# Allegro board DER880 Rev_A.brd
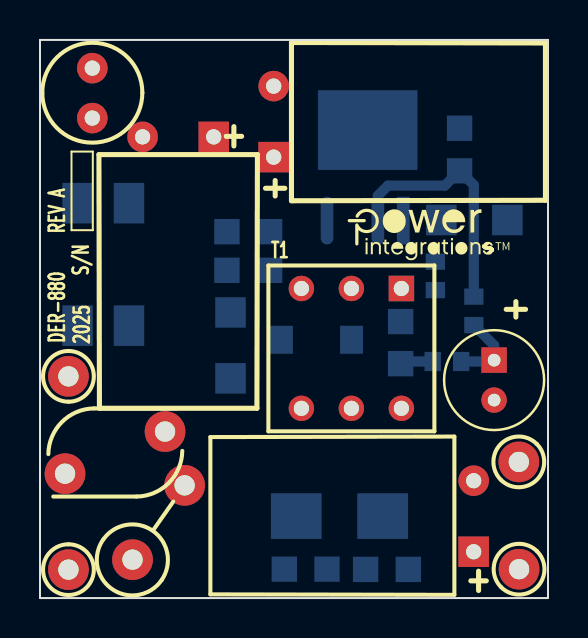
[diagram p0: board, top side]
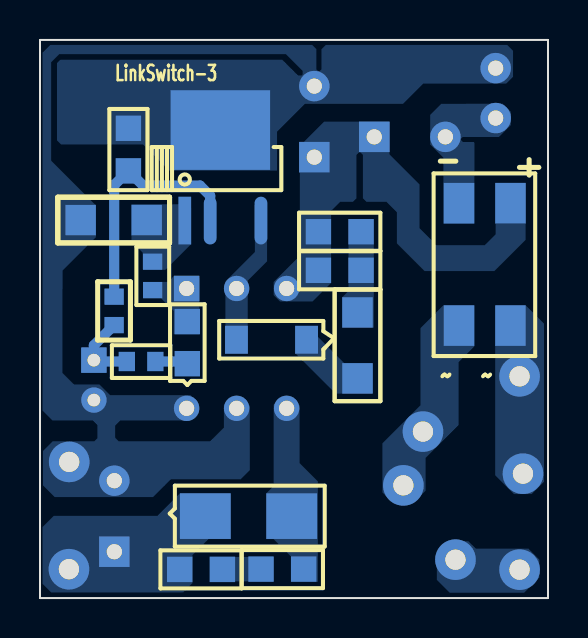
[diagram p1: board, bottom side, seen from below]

Outline 25.4 x 27.94 mm; copper layers: TOP, BOTTOM. Coordinates in mm from the lower left corner of the outline.
Outline path: 0,27.94 0,0 25.4,0 25.4,27.94 0,27.94

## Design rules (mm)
constraint set DEFAULT: min track width 0.508

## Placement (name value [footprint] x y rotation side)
BR1  B10S-G  [PISMSOIC4]  4.45 13.64 180 bottom
C1  3.3 uF  [PIPOLCAPCLYD320LS140030]  6.91 23.09 180 top
C2  3.3 uF  [PIPOLCAPCLYD320LS140030#2]  11.68 23.85 270 top
C3  10 uF  [PIPOLCAPCLYD5MMLS2MM025]  22.71 10.91 270 top
C4  1 uF  [PISMC0805]  20.98 21.39 90 bottom
C5  470 pF  [PISMC0805]  11.48 18.34 180 bottom
C7  470 pF  [PISMC0805]  16.28 1.44 0 bottom
C8  470  uF  [PIPOLCAPCLYD320LS140030]  21.68 4.1 90 top
D2  BAV20WS-7-F  [PISMDSOD323]  18.03 11.73 90 bottom
D3  S1ML  [PI_SM_SOD-123_12]  12.07 12.93 0 bottom
D4  SS110-TP  [PISMDO214AC12]  17.13 4.1 180 bottom
GND  -  [PITPKEYSTONE100X100]  23.94 6.82 315 top
L  BLK  [PITPKEYSTONE100X100]  1.42 1.42 0 top
L1  680 uH  [PICHOKETOKINVD216H413LS098D030]  2.62 24.03 90 top
N  WHT  [PITPKEYSTONE100X100]  1.42 11.1 0 top
NOREF  -  []  0 27.94 0 top
NOREF#2  -  []  0 0 90 top
NOREF#3  -  []  14.83 19.38 0 top
R1  100 k  [PISMR0805]  11.48 16.41 180 bottom
R2  470  [PISMR1206]  9.53 14.3 270 bottom
R3  57.6 k  [PISMR0603]  19.77 15.42 90 bottom
R4  12.7 k  [PISMR1206]  20.07 18.92 0 bottom
R5  9.1 k  [PISMR0603]  21.69 15.09 270 bottom
R6  10  [PISMR0603]  21.06 11.84 180 bottom
R8  15  [PISMR0805]  12.22 1.45 0 bottom
RF1  8.2  [PI12WRESD180LS575040]  4.63 1.92 55 top
RV1  275 Vac  [PI_DISC276X181_LS200X83D040]  6.25 6.23 180 top
T1  EE8.3  [PI_BOBBIN_EE8_3H6P]  15.57 12.5 270 top
U1  LNK6404D  [PISMSO8DNSHORT5678]  18.16 18.9 180 bottom
UNK+5V  RED  [PITPKEYSTONE100X100]  23.95 1.44 315 top

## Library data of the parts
BR1 = DIODE BRIDGE_~~+-: alternate symbols: (pi_sm_soic4_slot)
C1 C2 C8 = CAP POL: alternate symbols: (pipolcapclyd320ls140030430h)
C3 = CAP POL
C4 C5 C7 = CAP NP
D2 D3 = DIODE
D4 = DIODE SCHOTTKY
GND = TESTPOINT_PITPKEYSTONE100X100_B
L = TESTPOINT: alternate symbols: (TP_TH_CR2_D1_1)
L1 = INDUCTOR
N UNK+5V = TESTPOINT
R1-R6 R8 = R
RF1 = RF: alternate symbols: (pi1wvresd120ls200d040)
RV1 = VARISTOR
T1 = BEE8_3_6P
U1 = LNK6404

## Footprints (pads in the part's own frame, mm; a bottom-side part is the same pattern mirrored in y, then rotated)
PI12WRESD180LS575040
  round 2.032 hole 1.016: 1(0,0) 2(4.542,0)
PI_BOBBIN_EE8_3H6P
  rect 1.27x1.27 hole 0.762: 1(-3,2.5)
  round 1.27 hole 0.762: 2(-3,0) 3(-3,-2.5) 4(3,-2.5) 5(3,0) 6(3,2.5)
PI_DISC276X181_LS200X83D040
  round 2.032 hole 1.016: 1(0,-2.108) 2(5.001,0)
PI_SM_SOD-123_12
  rect 1.143x1.397 smd: 1(0,0) 2(3.505,0)
PICHOKETOKINVD216H413LS098D030
  round 1.524 hole 0.762: 1(0,0) 2(2.5,0)
PIPOLCAPCLYD5MMLS2MM025
  rect 1.27x1.27 hole 0.635: 1(-1,0)
  round 1.27 hole 0.635: 2(1,0)
PIPOLCAPCLYD320LS140030
  rect 1.524x1.524 hole 0.762: 1(-1.778,0)
  round 1.524 hole 0.762: 2(1.778,0)
PIPOLCAPCLYD320LS140030#2
  rect 1.524x1.524 hole 0.762: 1(1.778,0)
  round 1.524 hole 0.762: 2(-1.778,0)
PISMC0805
  rect 1.27x1.27 smd: 1(0,0) 2(2.134,0)
PISMDO214AC12
  rect 2.54x2.286 smd: 1(0,0) 2(4.318,0)
PISMDSOD323
  rect 1.27x1.27 smd: 1(0,0) 2(2.108,0)
PISMR0603
  rect 0.813x0.965 smd: 1(0,0) 2(1.422,0)
PISMR0805
  rect 1.27x1.27 smd: 1(0,0) 2(2.134,0)
PISMR1206
  rect 1.524x1.524 smd: 1(0,0) 2(3.302,0)
PISMSO8DNSHORT5678
  rect 0.635x2.388 smd: 1(0,0)
  oval 0.635x2.388 smd: 2(1.27,0) 4(3.81,0) 5(3.81,4.978) 6(2.54,4.978) 7(1.27,4.978) 8(0,4.978)
PISMSOIC4
  rect 1.524x2.032 smd: 1(0,0) 2(2.57,0) 3(2.57,6.129) 4(0,6.129)
PITPKEYSTONE100X100
  round 2.032 hole 1.016: 1(0,0)

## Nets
SOURCE: U1.6 U1.7 U1.8
N02548: BR1.3 C1.1 C2.1 C5.1 R1.1 T1.3
N02674: BR1.4 C1.2 L1.1
N03502: C2.2 C3.2 C4.2 C8.2 GND.1 L1.2 R4.2 T1.5 T1.6 U1.5(S)
N03550: C4.1 R5.1 U1.2
N04036: R3.2 R4.1 U1.1
N04459: C3.1 R5.2 R6.1
N04496: D2.1 R6.2
N04748: D3.2 T1.2 U1.4
N04766: D2.2 R3.1 T1.1
N04877: D4.2 R8.1 T1.4
N04912: C7.1 R8.2
N04991: C7.2 C8.1 D4.1 UNK+5V.1
N06108: BR1.1 RF1.2 RV1.1
N06154: L.1 RF1.1
N06177: BR1.2 N.1 RV1.2
N12152: C5.2 R1.2 R2.1
N12184: D3.1 R2.2

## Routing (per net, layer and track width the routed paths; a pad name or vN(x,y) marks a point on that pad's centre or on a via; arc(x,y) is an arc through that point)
N03550: length 12.4
  BOTTOM w0.508: U1.2 16.89,20.14 17.4,20.65 20.24,20.65 C4.1 21.69,20.67 R5.1
N04459: length 3.9
  BOTTOM w0.508: R6.1 22.64,11.84 C3.1 22.71,12.65 R5.2
N04496: length 1.6
  BOTTOM w0.508: D2.1 18.14,11.84 R6.2

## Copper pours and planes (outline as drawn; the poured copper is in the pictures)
N02548 on BOTTOM: 7.56,17.75 6.17,16.37 2.68,16.37 1.12,17.93 1.12,20.78 2.62,20.78 2.62,18.21 3.16,17.67 5.57,17.67 6.42,18.52 6.42,20.71 7.92,22.21 7.92,23.85 11.19,23.85 12.41,22.63 12.41,17.13 13.72,15.82 13.72,15.16 13.4,14.85 11.77,14.85 10.85,15.77 10.85,19.38 10.39,19.84 9.75,19.84 9.58,20.01 9.58,22.18 9.44,22.32 9.39,22.32 9.25,22.19 9.25,20.02 9.08,19.84 8.08,19.84 7.56,19.32
N02674 on BOTTOM: 3.68,18.75 3.68,21.18 3.68,21.19 3.68,22.79 3.72,22.83 4.25,22.83 4.36,22.94 4.36,22.99 4.27,23.08 2.45,23.08 1.86,23.68 1.86,24.34 2.26,24.75 4.09,24.75 4.09,24.74 5.34,24.74 5.89,24.19 5.89,22.71 5.23,22.05 5.23,18.75
N03502 on BOTTOM (solid shape): 18.87,21.44 13.89,21.44 13.89,25.43 18.87,25.43
N03502 on BOTTOM: 14.91,9.63 15.32,10.03 15.82,10.03 16.21,9.65 16.21,8.53 16.89,7.85 21.46,7.85 21.64,8.03 21.64,8.64 21.39,8.89 17.91,8.89 17.54,9.26 17.54,9.82 17.88,10.16 21.89,10.16 22.43,10.69 23.7,10.69 24.28,11.27 24.28,15.47 24.27,15.48 24.27,16.4 22.61,18.06 22.61,19.66 24.84,21.89 24.84,26.82 24.43,27.23 13.11,27.23 12.27,26.39 12.27,26.21 12.32,26.16 12.5,26.16 13.28,26.95 24.38,26.95 24.55,26.78 24.55,22.91 24.35,22.71 20.24,22.71 18.95,21.41 18.95,21.4 13.55,21.4 13.55,23.35 12.4,24.5 12.16,24.74 7.25,24.74 6.23,25.76 2.09,25.76 1.75,26.1 1.75,27.4 2.04,27.69 11.11,27.69 11.33,27.47 11.33,26.47 11.43,26.37 11.48,26.37 11.58,26.47 11.58,27.48 11.79,27.69 24.88,27.69 25.27,27.3 25.27,9.39 24.78,8.89 22.76,8.89 22.53,8.66 22.53,8 22.68,7.85 24.77,7.85 25.25,7.37 25.25,5.64 24.66,5.05 19.75,5.05 18.85,5.95 15.36,5.95 14.91,6.4
N04036 on BOTTOM: 17.84,17.7 17.86,17.7 19.13,16.43 20.24,16.43 20.27,16.46 20.27,17.3 20.83,17.86 20.83,19.71 18.01,19.71 17.84,19.54
N04748 on BOTTOM: 14.05,16.86 15.01,15.89 15.01,12.24 16.13,12.24 16.13,15.85 14.66,17.32 14.66,19.71 14.53,19.84 14.15,19.84 14.05,19.74
N04766 on BOTTOM: 18.72,13.21 18.72,14.38 19.35,15.01 20.24,15.01 20.24,15.82 19,15.82 18.69,16.13 17.53,16.13 17.43,16.04 17.43,13.21
N04877 on BOTTOM: 13.36,10.03 13.72,9.68 13.72,5.61 14.08,5.25 14.08,2.95 13.72,2.95 12.86,2.09 12.85,2.08 12.85,0.81 11.51,0.81 11.51,5.84 12.42,6.76 12.42,9.65 12.8,10.03
N04912 on BOTTOM: 13.74,0.84 16.89,0.84 16.89,2.06 13.71,2.06 13.71,0.86
N04991 on BOTTOM: 24.71,4.11 25.27,3.56 25.27,0.71 24.84,0.28 18.33,0.28 18.33,0.28 18.24,0.28 17.78,0.75 17.78,2.15 16.97,2.95 15.87,2.95 15.87,5.24 18.4,5.24 19.53,4.11
N06108 on BOTTOM: 6.38,13.51 5.23,14.66 3.68,14.66 3.68,12.6 4.47,11.81 4.47,8.66 6.12,7.01 6.12,5.37 6.74,4.76 7.75,4.76 8.28,5.29 8.28,7.75 6.38,9.65
N06154 on BOTTOM: 3.61,2.48 3.97,2.84 5.03,2.84 5.56,2.31 5.56,0.91 4.91,0.27 1.19,0.27 0.43,1.02 0.43,1.93 0.98,2.48
N06177 on BOTTOM: 0.2,13.74 1.12,14.66 2.64,14.66 2.64,6.15 1.7,5.21 0.81,5.21 0.2,5.82
N12152 on BOTTOM: 9.98,18.97 8.74,18.97 8.71,18.94 8.71,13.54 8.89,13.54 8.89,13.54 10.16,13.54 10.16,13.54 10.29,13.54 10.29,15.06 9.98,15.37
N12184 on BOTTOM: 12.62,13.61 11.51,13.61 11.51,13.08 10.19,11.76 8.76,11.76 8.76,10.24 10.62,10.24 12.62,12.24

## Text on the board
Ref Des/Silkscreen Bottom: LinkSwitch-3
Ref Des/Silkscreen Top: REV A | DER-880 | S/N | 2025
User.5: 1.  THROUGH HOLES ARE PLATED THROUGH. | EXCEPTIONS WILL BE NOTED IN DRILL CHART "NOTE". | 2.  MATERIAL: BASE MATERIAL LAMINATED EPOXY | UL APPROVED MANUFACTURED SOURCE FOR FR4. | 3.  SOLDER PLATE WILL BE RoHS COMPLIANT. | 4.  SOLDER MASK LPI (LIQUID PHOTO IMAGEABLE) BOTH SIDES. COLOR GREEN. | SOLDER MASK (REGISTRATION) -0/+0.003" | 5.  SILKSCREEN TOP/BOTTOM SIDE. COLOR WHITE. (MIN.WIDTH 0.005" MAX.WIDTH 0.010") | 6.  FINISH TO BE SMOBC. | 7.  LEAD FREE HASL (HOT AIR SOLDER LEVEL) OR RoHS COMPLIANT. | 8.  BOARD DIMENSION +/- 0.005" | 9.  DRILL TOLERANCE +/- 0.003" | 10. TRACE WIDTH UNDER 0.010" +/- 0.002" | TRACE WIDTH OVER 0.011" +/- 0.005" | 11. TRACE SPACE +/- 0.003" | 12. MATERIAL FR4 COPPER 2 OZ BOARD THICKNESS 0.062" | NOTES: UNLESS OTHERWISE SPECIFIED
User.8: FIGURE | FINISHED_SIZE | 25.0 | 30.0 | 40.0 | DRILL CHART: TOP to BOTTOM | ALL UNITS ARE IN MILS | PLATED | QTY | 2 | 14 | 8
